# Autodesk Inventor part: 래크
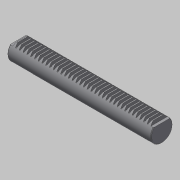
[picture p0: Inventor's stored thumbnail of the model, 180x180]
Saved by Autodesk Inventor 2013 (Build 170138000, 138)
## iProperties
Created: 2019-06
Part Number: 래크
Material: 스테인리스강
Document SubType Name: Modeling
Designer: mduedu
Density: 1 g/cm^3
Author: mduedu
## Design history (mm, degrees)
sketch "스케치1"
  geometry: L1 (0, 0)-(240, 0); L2 (240, 0)-(240, 34); L3 (240, 34)-(0, 34); L4 (0, 34)-(0, 0)
  constraints: 8 end point, 2 parallel, 1 horizontal, 1 perpendicular
  dimensions: "d0" = 240 distance of L1.start L1.end; "d1" = 34 distance of L1.end L2.end
extrude "돌출1" new body sketch "스케치1" stored distance "d2" = 36; taper "d3" = 0 deg
sketch "스케치2"
  geometry: L1 (0, 0)-(240, 0) reference; L2 (240, 0)-(240, 34) reference; L3 (240, 34)-(0, 34) reference; L4 (0, 34)-(0, 0) reference; L5 (9.44, 29.5)-(10.76, 29.5); L6 (12.398, 34)-(7.802, 34); L7 (10.1, 34)-(10.1, 29.5); L8 (7.802, 34)-(9.44, 29.5); L9 (12.398, 34)-(10.76, 29.5); L10 (8.53, 32)-(11.67, 32); 1 further point
  constraints: 12 end point, 2 midpoint, 2 point on line, 1 collinear, 1 horizontal, 1 parallel, 1 perpendicular, 1 symmetric about line
  dimensions: "d4" = 20 deg angle of L9 L7; "d5" = 2 distance between parallel lines of L10 L6; "d7" = 4.5 distance between parallel lines of L5 L6 (= 2.25 x d5); "d8" = 3.14 distance of L10.start L10.end; "d9" = 10.1 distance between parallel lines of L4 L7
extrude "돌출2" cut sketch "스케치2" stored distance "d10" = 36; taper "d11" = 0 deg
sketch "스케치3"
  geometry: L1 (235.52, 29.5)-(233.882, 34) reference; L2 (233.882, 34)-(232.198, 34) reference; L3 (232.198, 34)-(230.56, 29.5) reference; L4 (230.56, 29.5)-(229.24, 29.5) reference; L5 (229.24, 29.5)-(227.602, 34) reference; L6 (227.602, 34)-(225.918, 34) reference; L7 (225.918, 34)-(224.28, 29.5) reference; L8 (224.28, 29.5)-(222.96, 29.5) reference; L9 (222.96, 29.5)-(221.322, 34) reference; L10 (221.322, 34)-(219.638, 34) reference; L11 (219.638, 34)-(218, 29.5) reference; L12 (218, 29.5)-(216.68, 29.5) reference; L13 (216.68, 29.5)-(215.042, 34) reference; L14 (215.042, 34)-(213.358, 34) reference; L15 (213.358, 34)-(211.72, 29.5) reference; L16 (211.72, 29.5)-(210.4, 29.5) reference; L17 (210.4, 29.5)-(208.762, 34) reference; L18 (208.762, 34)-(207.078, 34) reference; L19 (207.078, 34)-(205.44, 29.5) reference; L20 (205.44, 29.5)-(204.12, 29.5) reference; L21 (204.12, 29.5)-(202.482, 34) reference; L22 (202.482, 34)-(200.798, 34) reference; L23 (200.798, 34)-(199.16, 29.5) reference; L24 (199.16, 29.5)-(197.84, 29.5) reference; L25 (197.84, 29.5)-(196.202, 34) reference; L26 (196.202, 34)-(194.518, 34) reference; L27 (194.518, 34)-(192.88, 29.5) reference; L28 (192.88, 29.5)-(191.56, 29.5) reference; L29 (191.56, 29.5)-(189.922, 34) reference; L30 (189.922, 34)-(188.238, 34) reference; L31 (188.238, 34)-(186.6, 29.5) reference; L32 (186.6, 29.5)-(185.28, 29.5) reference; L33 (185.28, 29.5)-(183.642, 34) reference; L34 (183.642, 34)-(181.958, 34) reference; L35 (181.958, 34)-(180.32, 29.5) reference; L36 (180.32, 29.5)-(179, 29.5) reference; L37 (179, 29.5)-(177.362, 34) reference; L38 (177.362, 34)-(175.678, 34) reference; L39 (175.678, 34)-(174.04, 29.5) reference; L40 (174.04, 29.5)-(172.72, 29.5) reference; L41 (172.72, 29.5)-(171.082, 34) reference; L42 (171.082, 34)-(169.398, 34) reference; L43 (169.398, 34)-(167.76, 29.5) reference; L44 (167.76, 29.5)-(166.44, 29.5) reference; L45 (166.44, 29.5)-(164.802, 34) reference; L46 (164.802, 34)-(163.118, 34) reference; L47 (163.118, 34)-(161.48, 29.5) reference; L48 (161.48, 29.5)-(160.16, 29.5) reference; L49 (160.16, 29.5)-(158.522, 34) reference; L50 (158.522, 34)-(156.838, 34) reference; L51 (156.838, 34)-(155.2, 29.5) reference; L52 (155.2, 29.5)-(153.88, 29.5) reference; L53 (153.88, 29.5)-(152.242, 34) reference; L54 (152.242, 34)-(150.558, 34) reference; L55 (150.558, 34)-(148.92, 29.5) reference; L56 (148.92, 29.5)-(147.6, 29.5) reference; L57 (147.6, 29.5)-(145.962, 34) reference; L58 (145.962, 34)-(144.278, 34) reference; L59 (144.278, 34)-(142.64, 29.5) reference; L60 (142.64, 29.5)-(141.32, 29.5) reference; L61 (141.32, 29.5)-(139.682, 34) reference; L62 (139.682, 34)-(137.998, 34) reference; L63 (137.998, 34)-(136.36, 29.5) reference; L64 (136.36, 29.5)-(135.04, 29.5) reference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; 1 further point
  constraints: 16 end point, 4 parallel, 2 horizontal, 2 perpendicular
extrude "돌출3" cut sketch "스케치3" stored distance "d18" = 36; taper "d19" = 0 deg
sketch "스케치4"
  geometry: L1 (4.48, 29.5)-(0, 29.5) reference; L2 (0, 29.5)-(0, 0) reference; L3 (0, 0)-(240, 0) reference; L4 (240, 0)-(240, 29.5) reference; L5 (240, 29.5)-(235.52, 29.5) reference; L6 (235.52, 29.5)-(233.882, 34) reference; L7 (233.882, 34)-(232.198, 34) reference; L8 (232.198, 34)-(230.56, 29.5) reference; L9 (230.56, 29.5)-(229.24, 29.5) reference; L10 (229.24, 29.5)-(227.602, 34) reference; L11 (227.602, 34)-(225.918, 34) reference; L12 (225.918, 34)-(224.28, 29.5) reference; L13 (224.28, 29.5)-(222.96, 29.5) reference; L14 (222.96, 29.5)-(221.322, 34) reference; L15 (221.322, 34)-(219.638, 34) reference; L16 (219.638, 34)-(218, 29.5) reference; L17 (218, 29.5)-(216.68, 29.5) reference; L18 (216.68, 29.5)-(215.042, 34) reference; L19 (215.042, 34)-(213.358, 34) reference; L20 (213.358, 34)-(211.72, 29.5) reference; L21 (211.72, 29.5)-(210.4, 29.5) reference; L22 (210.4, 29.5)-(208.762, 34) reference; L23 (208.762, 34)-(207.078, 34) reference; L24 (207.078, 34)-(205.44, 29.5) reference; L25 (205.44, 29.5)-(204.12, 29.5) reference; L26 (204.12, 29.5)-(202.482, 34) reference; L27 (202.482, 34)-(200.798, 34) reference; L28 (200.798, 34)-(199.16, 29.5) reference; L29 (199.16, 29.5)-(197.84, 29.5) reference; L30 (197.84, 29.5)-(196.202, 34) reference; L31 (196.202, 34)-(194.518, 34) reference; L32 (194.518, 34)-(192.88, 29.5) reference; L33 (192.88, 29.5)-(191.56, 29.5) reference; L34 (191.56, 29.5)-(189.922, 34) reference; L35 (189.922, 34)-(188.238, 34) reference; L36 (188.238, 34)-(186.6, 29.5) reference; L37 (186.6, 29.5)-(185.28, 29.5) reference; L38 (185.28, 29.5)-(183.642, 34) reference; L39 (183.642, 34)-(181.958, 34) reference; L40 (181.958, 34)-(180.32, 29.5) reference; L41 (180.32, 29.5)-(179, 29.5) reference; L42 (179, 29.5)-(177.362, 34) reference; L43 (177.362, 34)-(175.678, 34) reference; L44 (175.678, 34)-(174.04, 29.5) reference; L45 (174.04, 29.5)-(172.72, 29.5) reference; L46 (172.72, 29.5)-(171.082, 34) reference; L47 (171.082, 34)-(169.398, 34) reference; L48 (169.398, 34)-(167.76, 29.5) reference; L49 (167.76, 29.5)-(166.44, 29.5) reference; L50 (166.44, 29.5)-(164.802, 34) reference; L51 (164.802, 34)-(163.118, 34) reference; L52 (163.118, 34)-(161.48, 29.5) reference; L53 (161.48, 29.5)-(160.16, 29.5) reference; L54 (160.16, 29.5)-(158.522, 34) reference; L55 (158.522, 34)-(156.838, 34) reference; L56 (156.838, 34)-(155.2, 29.5) reference; L57 (155.2, 29.5)-(153.88, 29.5) reference; L58 (153.88, 29.5)-(152.242, 34) reference; L59 (152.242, 34)-(150.558, 34) reference; L60 (150.558, 34)-(148.92, 29.5) reference; L61 (148.92, 29.5)-(147.6, 29.5) reference; L62 (147.6, 29.5)-(145.962, 34) reference; L63 (145.962, 34)-(144.278, 34) reference; L64 (144.278, 34)-(142.64, 29.5) reference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; 1 further point
  constraints: 8 end point, 2 parallel, 1 horizontal, 1 perpendicular, 1 point on line
  dimensions: "d20" = 36 distance between parallel lines of L156 L2; "d21" = 10 distance between parallel lines of L4 L154; "d22" = 194 distance between parallel lines of L154 L156 (derived); "d23" = 4 distance between parallel lines of L3 L155
extrude "돌출4" cut sketch "스케치4" stored distance "d24" = 36; taper "d25" = 0 deg
sketch "스케치5"
  geometry: L1 (36, 0)-(0, 0) reference; C1 r 18 at (18, 18); 2 further points
  constraints: 1 centre point, 1 midpoint, 1 tangent, 1 vertical alignment
  dimensions: "d26" = 36 diameter of C1
extrude "돌출5" sketch "스케치5" stored distance "d27" = 36; taper "d28" = 0 deg
chamfer "모따기1" distance "d29" = 1; stored, may be unused: second distance "d30" = 2, angle "d31" = 45 deg
node "솔리드1"
pattern_linear "직사각형 패턴1" dims "d14" = 6.28, "d17" = 6.28
node "투영된 루프1"
node "투영된 루프2"
node "투영된 루프3"
